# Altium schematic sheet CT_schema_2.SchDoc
size 322 x 229 mm
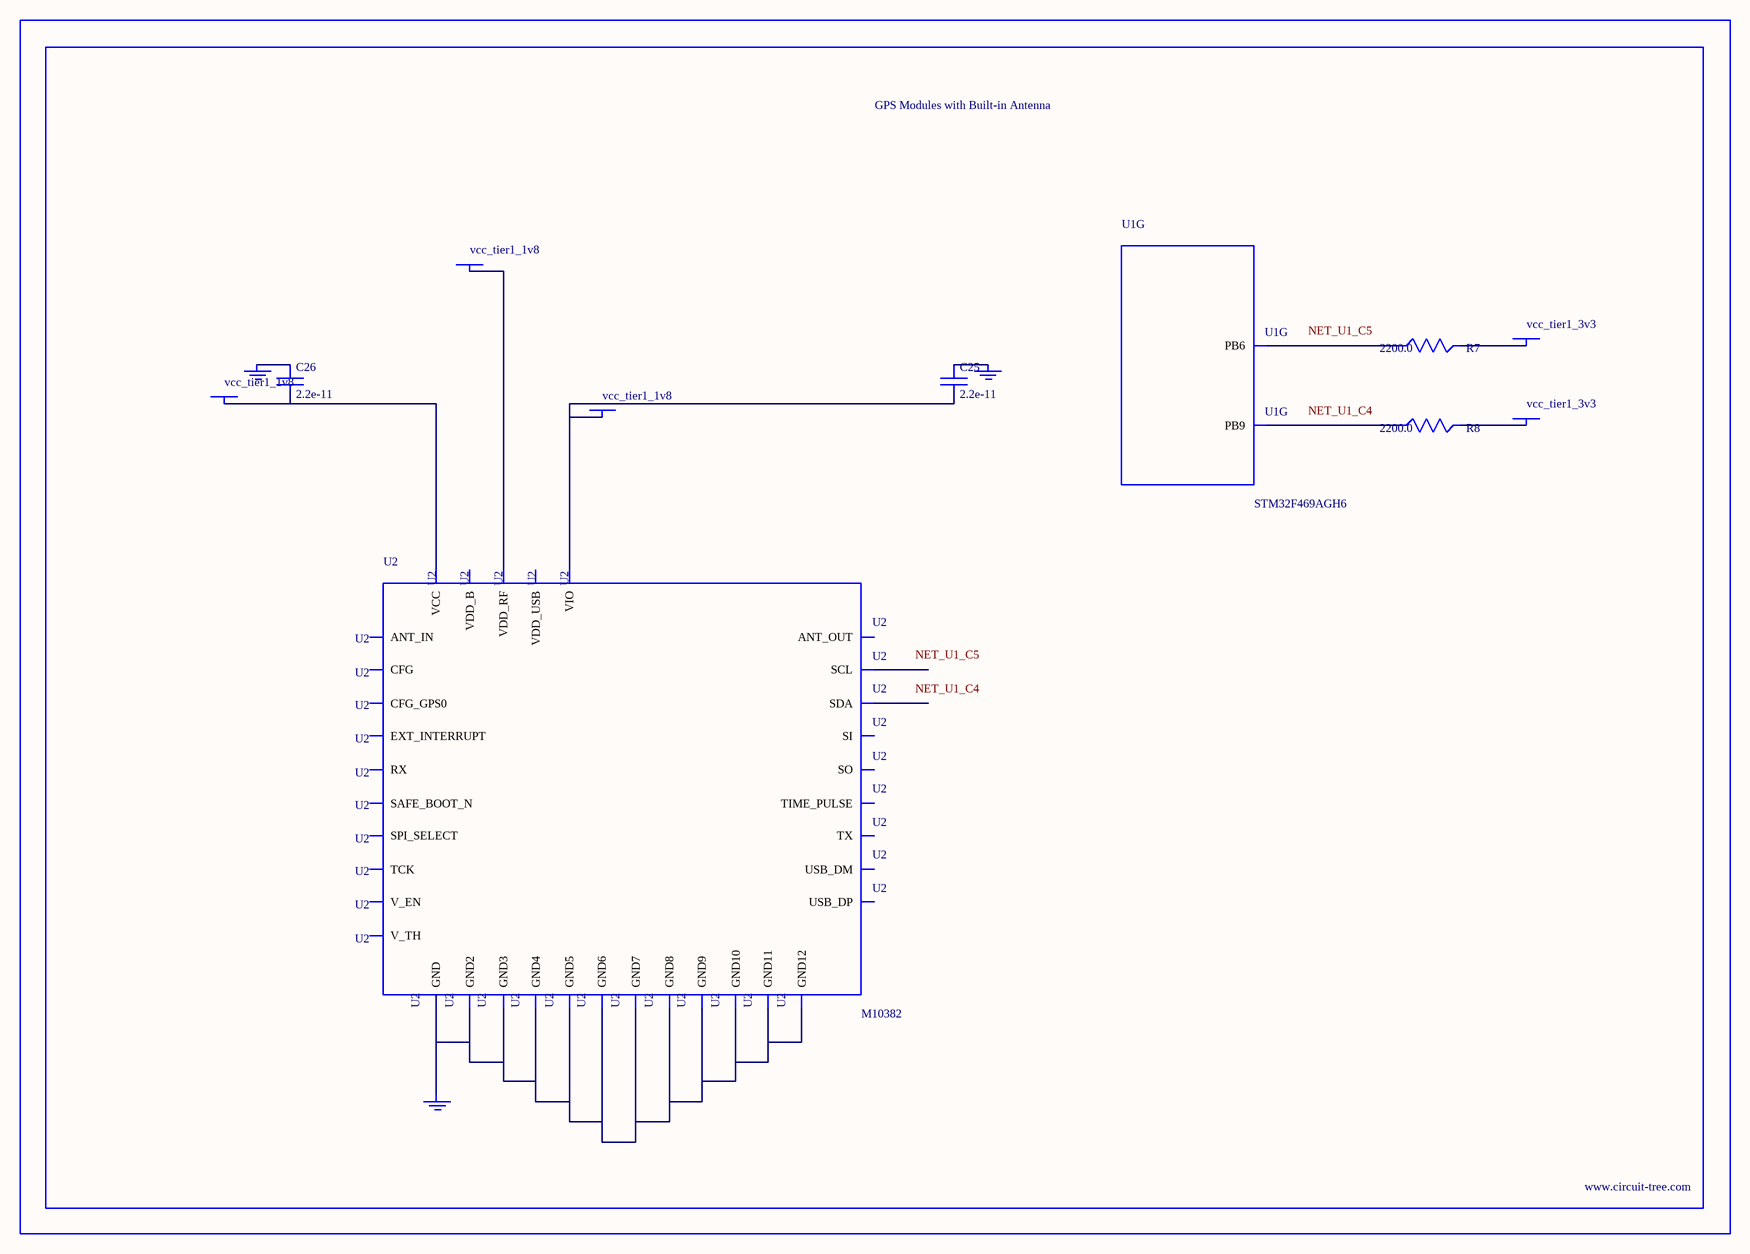
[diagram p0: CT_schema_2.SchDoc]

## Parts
BORDER1  (no value)
C25  2.2e-11  [C0402]
C26  2.2e-11  [C0402]
GND_INSTANCE_1_0  (no value)
GND_INSTANCE_1_1  (no value)
GND_INSTANCE_1_2  (no value)
POWER_INSTANCE_1_0  vcc_tier1_1v8
POWER_INSTANCE_1_1  vcc_tier1_1v8
POWER_INSTANCE_1_2  vcc_tier1_1v8
POWER_INSTANCE_1_3  vcc_tier1_3v3
POWER_INSTANCE_1_4  vcc_tier1_3v3
R7  2200.0  [R0603]
R8  2200.0  [R0603]
U1  STM32F469AGH6  [UFBGA169]  (part G of 14)
U2  M10382  [M10382]

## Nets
NetC25_1: C25.1 GND_INSTANCE_1_0.0(GND)
NetC25_2: C25.2 POWER_INSTANCE_1_0.0(PWR) U2.5(VIO)
NetC26_1: C26.1 GND_INSTANCE_1_1.0(GND)
NetC26_2: C26.2 POWER_INSTANCE_1_2.0(PWR) U2.27(VCC)
NetGND_INSTANCE_1_2_0: GND_INSTANCE_1_2.0(GND) U2.2(GND) U2.4(GND2) U2.14(GND3) U2.17(GND4) U2.21(GND5) U2.24(GND6) U2.26(GND7) U2.28(GND8) U2.33(GND9) U2.34(GND10) U2.35(GND11) U2.36(GND12)
NetPOWER_INSTANCE_1_1_0: POWER_INSTANCE_1_1.0(PWR) U2.25(VDD_RF)
NetPOWER_INSTANCE_1_3_0: POWER_INSTANCE_1_3.0(PWR) R7.2
NetPOWER_INSTANCE_1_4_0: POWER_INSTANCE_1_4.0(PWR) R8.2
NetR7_1: R7.1 U1.C5(PB6)
NetR8_1: R8.1 U1.C4(PB9)

Not connected (* = marked no-connect by the designer): U2 1(ANT_IN) 3(ANT_OUT) 6(USB_DP) 7(USB_DM) 8(SO) 9(CFG_GPS0) 10(SPI_SELECT) 11(TX) 12(V_TH) 13(RX) 15(VDD_B) 16(SI) 18(SDA) 19(SCL) 20(SAFE_BOOT_N) 22(TCK) 23(TIME_PULSE) 29(EXT_INTERRUPT) 30(V_EN) 31(CFG) 32(VDD_USB)

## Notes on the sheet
- Labels drawn without touching a wire or pin: NET_U1_C4, NET_U1_C5

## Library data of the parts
BORDER1 = BORDER_PAGE1
C25 C26 = C0402C220K3RAC
GND_INSTANCE_1_0-GND_INSTANCE_1_2 = GND
POWER_INSTANCE_1_0-POWER_INSTANCE_1_4 = PWR
R7 R8 = RC0603JR-072K2L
